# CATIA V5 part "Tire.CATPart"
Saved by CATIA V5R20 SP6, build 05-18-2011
Part number: Tire
Bounding box of the stored display mesh (mm): x -299.997 to 299.997, y 355 to 505, z -299.993 to 299.993
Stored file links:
  E:\#03 University\#02 영남 이공대\#01 2021\#02 여름 방학\#01 Documents\K-Move Page02 ASD01\Tire.CATPart

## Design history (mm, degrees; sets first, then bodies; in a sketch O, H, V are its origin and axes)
Set1 "Reference Data"
  Point1 "Center Point": (0, 0, 0)
Body1 (main body)
  Body2
    Sketch1 on xy-plane, origin (0, 0, 0), H (0, 1, 0), V (-1, 0, 0)
      axis line L1 (0, 0) -> (522.8325, 0)
      line L2 (355, 100) -> (355, 300)
      line L3 (355, 300) -> (505, 300)
      line L4 (505, 300) -> (505, 100)
      construction line L5 (430, 300) -> (430, 0)
      point P4 (430, 300)
      point P5 (430, 0)
      line L6 (505, 100) -> (475, 100)
      point P6 (475, 100)
      line L7 (475, 100) -> (475, 0)
      point P7 (475, 0)
      point P9 (385, 100)
      line L8 (355, 100) -> (385, 100)
      point P10 (385, 0)
      line L9 (385, 100) -> (385, 0)
      distance L2 L4 = 150
      distance L1 L3 = 300
      distance V L5 = 430
      distance L7 L4 = 30
      distance L6 L1 = 100
      horizontal: L1 H, L3 H, L6 H
      vertical: L2 V, L4 V, L5 V, L7 V
      midpoint: P4 L3
      coincidence: P5 L1, P7 L1
      symmetry: P6 P9 L5, L6 L8 L5, P7 P10 L5, L7 L9 L5
    Shaft1: profile Sketch1, axis Sketch1.L1, angle 360
    Fillet1: radius 30, on edge [face of Shaft1 from Sketch1.L3 | face of Shaft1 from Sketch1.L4]; edge [face of Shaft1 from Sketch1.L2 | face of Shaft1 from Sketch1.L3]
    Fillet2: radius 20, on edge [face of Shaft1 from Sketch1.L4 | face of Shaft1 from Sketch1.L6]; edge [face of Shaft1 from Sketch1.L6 | face of Shaft1 from Sketch1.L7]
  Assemble1: tool Body2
